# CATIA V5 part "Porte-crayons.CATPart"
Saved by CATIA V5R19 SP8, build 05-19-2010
Part number: Ratelier_Pot_Crayons
Publications: "Face latéralle Ratelier", "Face bas ratelier", "Face haut ratelier"
Bounding box of the stored display mesh (mm): x -3 to 37, y 0 to 80, z -2 to 53
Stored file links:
  D:\Documents\1_Travail\1 - ac-limoges.fr\OneDrive - ac-limoges.fr\STI2D_Turgot\3 - Supports\Pot_à_Crayons\Maquette numérique\Maquette_eleve\Porte-crayons.CATPart
  D:\Documents\1_Travail\1 - ac-limoges.fr\OneDrive - ac-limoges.fr\STI2D_Turgot\3 - Supports\Pot_à_Crayons\Maquette numérique\Pot_Crayons.CATProduct
  D:\Documents\1_Travail\1 - ac-limoges.fr\OneDrive - ac-limoges.fr\STI2D_Turgot\3 - Supports\Pot_à_Crayons\Maquette numérique\Porte-crayons_Plaque.CATPart
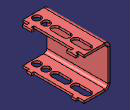
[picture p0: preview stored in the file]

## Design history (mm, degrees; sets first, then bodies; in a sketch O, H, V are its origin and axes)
SheetMetalParameters1: Thickness 3, BendRadius 4, KFactor 0.356492 {= log(min(100,max(20*SheetMetalParameters1.BendRadius,SheetMetalParameters1.Thickness)/SheetMetalParameters1.Thickness))/log(100)/2}, ReliefRadialLength 1, ReliefAxialLength 2, MinimumBendRadius 0
Body1 "Porte crayon" (main body)
  Sketch1 on yz-plane, origin (0, 0, 0), H (0, 1, 0), V (0, 0, 1)
    line L1 (0, 50) -> (80, 50)
    line L2 (80, 50) -> (80, 0)
    line L3 (80, 0) -> (0, 0)
    line L4 (0, 0) -> (0, 50)
    distance L4 L2 = 80
    distance L1 L3 = 50
    horizontal: L1 H, L3 H
    vertical: L2 V, L4 V
    coincidence: L4 V, L3 H
  Wall1: Thickness 3, Profile Sketch1
  d_NewWallOnEdge1 "Pli Supérieur": NewWallOnEdge_Edge edge [face of Wall1 | face of Wall1], NewWallOnEdge_Length 40, NewWallOnEdge_HeightLimitOffset 3, NewWallOnEdge_WidthOffset1 0, NewWallOnEdge_WidthOffset2 0, NewWallOnEdge_Angle 90, NewWallOnEdge_BendRadiusValue 4 {= SheetMetalParameters1.BendRadius}, NewWallOnEdge_BendTable SheetMetalParameters1, KFacteur 0.356492 {= log(min(100,max(20*d_NewWallOnEdge1.Radius,SheetMetalParameters1.Thickness)/SheetMetalParameters1.Thickness))/log(100)/2}
  d_NewWallOnEdge2 "Pli Inférieur": NewWallOnEdge_Edge edge [face of Wall1 | face of Wall1], NewWallOnEdge_Length 37 {= d_NewWallOnEdge1.Length -SheetMetalParameters1.Thickness}, NewWallOnEdge_HeightLimitOffset 2, NewWallOnEdge_WidthOffset1 0, NewWallOnEdge_WidthOffset2 0, NewWallOnEdge_Angle 90, NewWallOnEdge_BendRadiusValue 4 {= SheetMetalParameters1.BendRadius}, NewWallOnEdge_BendTable SheetMetalParameters1, KFacteur 0.356492 {= log(min(100,max(20*d_NewWallOnEdge2.Radius,SheetMetalParameters1.Thickness)/SheetMetalParameters1.Thickness))/log(100)/2}
  Sketch2 on face of d_NewWallOnEdge1, origin (0, 0, 53), H (0, -1, 0), V (1, 0, 0)
    circle A1 centre (-19, 20) radius 5
    point P1 (-19, 20)
    circle A2 centre (-7, 20) radius 5
    point P2 (-7, 20)
    construction line L1 (-73, 20) -> (-58, 20)
    point P3 (-73, 20)
    point P4 (-58, 20)
    line L2 (-73, 25) -> (-58, 25)
    line L3 (-58, 15) -> (-73, 15)
    arc A3 centre (-58, 20) radius 5 from (-58, 25) to (-58, 15) cw
    arc A4 centre (-73, 20) radius 5 from (-73, 15) to (-73, 25) cw
    construction line L4 (-46, 20) -> (-31, 20)
    point P9 (-46, 20)
    point P10 (-31, 20)
    line L5 (-46, 25) -> (-31, 25)
    line L6 (-31, 15) -> (-46, 15)
    arc A5 centre (-31, 20) radius 5 from (-31, 25) to (-31, 15) cw
    arc A6 centre (-46, 20) radius 5 from (-46, 15) to (-46, 25) cw
    axis line L7 (-86.6067, 20) -> (23.8795, 20)
    point P15 (-86.6067, 20)
    reference intersected line E1 through (0, 0) direction (-1, 0) from face of Wall1
    reference intersected line E2 (-80, 4) -> (-80, 23) from face of d_NewWallOnEdge1
    distance L1 L2 = 5
    distance L4 L5 = 5
    radius A1 = 5
    radius A2 = 5
    distance A2 A1 = 2
    distance P3 P4 = 15
    distance A6 A3 = 2
    distance P9 P10 = 15
    distance L7 E1 = 20
    distance A4 E2 = 2
    distance A1 A5 = 2
    horizontal: L1 H, L4 H, L7 H
    tangency: A3 L2, A4 L2, A3 L3, A4 L3, A5 L5, A6 L5, A5 L6, A6 L6
    coincidence: P9 L1, P15 L1, P2 L7, P1 L7
  CutOut1 "Découpe Crayons": Direction Sketch2, EndLimit through (limit type 3), Orientation true, Profile Sketch2, StartLimit through (limit type 2)
  Sketch3 on face of d_NewWallOnEdge1, origin (0, 0, 53), H (0, -1, 0), V (1, 0, 0)
    line L1 (0, 31) -> (-8, 31)
    line L2 (-72, 34) -> (-75, 34)
    line L3 (0, 37) -> (0, 31)
    line L4 (-66, 31) -> (-66, 34)
    line L5 (-72, 31) -> (-72, 34)
    line L6 (-63, 34) -> (-63, 37)
    line L7 (-75, 34) -> (-75, 37)
    line L8 (-5, 34) -> (-5, 37)
    line L9 (-8, 31) -> (-8, 34)
    line L10 (-14, 34) -> (-14, 31)
    line L11 (-17, 37) -> (-17, 34)
    line L12 (-80, 37) -> (-80, 31)
    line L13 (-63, 37) -> (-17, 37)
    line L14 (-66, 34) -> (-63, 34)
    line L15 (-17, 34) -> (-14, 34)
    line L16 (-8, 34) -> (-5, 34)
    line L17 (-80, 31) -> (-72, 31)
    line L18 (-5, 37) -> (0, 37)
    line L19 (-75, 37) -> (-80, 37)
    line L20 (-14, 31) -> (-66, 31)
    reference intersected line E1 (-80, 37) -> (0, 37) from face of d_NewWallOnEdge1
    reference intersected line E2 (-80, 4) -> (-80, 23) from face of d_NewWallOnEdge1
    reference intersected line E3 (0, 23) -> (0, 4) from face of d_NewWallOnEdge1
    distance L5 L4 = 6 {= Sketch3.distance(L10 L9)}
    distance L6 L4 = 3 {= SheetMetalParameters1.Thickness}
    distance L9 L8 = 3 {= SheetMetalParameters1.Thickness}
    distance L10 L9 = 6 {= SheetMetalParameters1.Thickness *2}
    distance L11 L10 = 3 {= SheetMetalParameters1.Thickness}
    distance L7 L12 = 5
    distance L8 L3 = 5
    distance L1 L18 = 6 {= Sketch3.distance(L16 L1) *2}
    distance L16 L1 = 3 {= SheetMetalParameters1.Thickness}
    distance L7 L5 = 3 {= SheetMetalParameters1.Thickness}
    coincidence: L1 L20, L1 L17, L16 L15, L15 L14, L14 L2, L19 L13, L13 L18, L13 E1, L12 E2, L3 E3
    perpendicularity: L3 L1
  CutOut2 "Découpe Accroche haut": Direction Sketch3, EndLimit through (limit type 2), Orientation true, Profile Sketch3, StartLimit through (limit type 2)
  Sketch4 on face of d_NewWallOnEdge2, origin (0, 0, 1), H (0, -1, 0), V (1, 0, 0)
    point P1 (0, 31)
    line L1 (0, 31) -> (-8, 31)
    line L2 (-8, 31) -> (-8, 34)
    line L3 (-8, 34) -> (0, 34)
    line L4 (0, 34) -> (0, 31)
    point P5 (-14, 31)
    line L5 (-14, 31) -> (-66, 31)
    line L6 (-66, 31) -> (-66, 34)
    line L7 (-66, 34) -> (-14, 34)
    line L8 (-14, 34) -> (-14, 31)
    point P7 (-66, 34)
    point P9 (-72, 31)
    line L9 (-72, 31) -> (-80, 31)
    line L10 (-80, 31) -> (-80, 34)
    line L11 (-80, 34) -> (-72, 34)
    line L12 (-72, 34) -> (-72, 31)
    point P11 (-80, 34)
    reference intersected line E1 (-80, 34) -> (0, 34) from face of d_NewWallOnEdge2
    reference intersected line E2 (0, 23) -> (0, 4) from face of d_NewWallOnEdge2
    reference intersected line E3 (-80, 4) -> (-80, 23) from face of d_NewWallOnEdge2
    reference intersected line E4 through (0, 31) direction (1, 0) from face of CutOut2
    reference intersected line E5 through (-72, 0) direction (0, 1) from face of CutOut2
    reference intersected line E6 through (-66, 0) direction (0, 1) from face of CutOut2
    reference intersected line E7 through (-8, 0) direction (0, 1) from face of CutOut2
    reference intersected line E8 through (-14, 0) direction (0, -1) from face of CutOut2
    coincidence: P1 V, P5 L1, P7 L3, P9 L1, P11 L3, L1 L5, L5 L9, L3 E1, L4 E2, L10 E3, L9 E4, L12 E5, E6 L6, E7 L2, L8 E8
    horizontal: L1 H, L3 H, L5 H, L7 H, L9 H, L11 H
    vertical: L2 V, L4 V, L6 V, L8 V, L10 V, L12 V
  CutOut3 "Découpe Accroche bas": Direction Sketch4, EndLimit through (limit type 2), Orientation true, Profile Sketch4, StartLimit through (limit type 2)
Body2 "Porte crayon à plat"
  Solid1 "Solide.1 ( Vue à plat )": linked copy from another document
